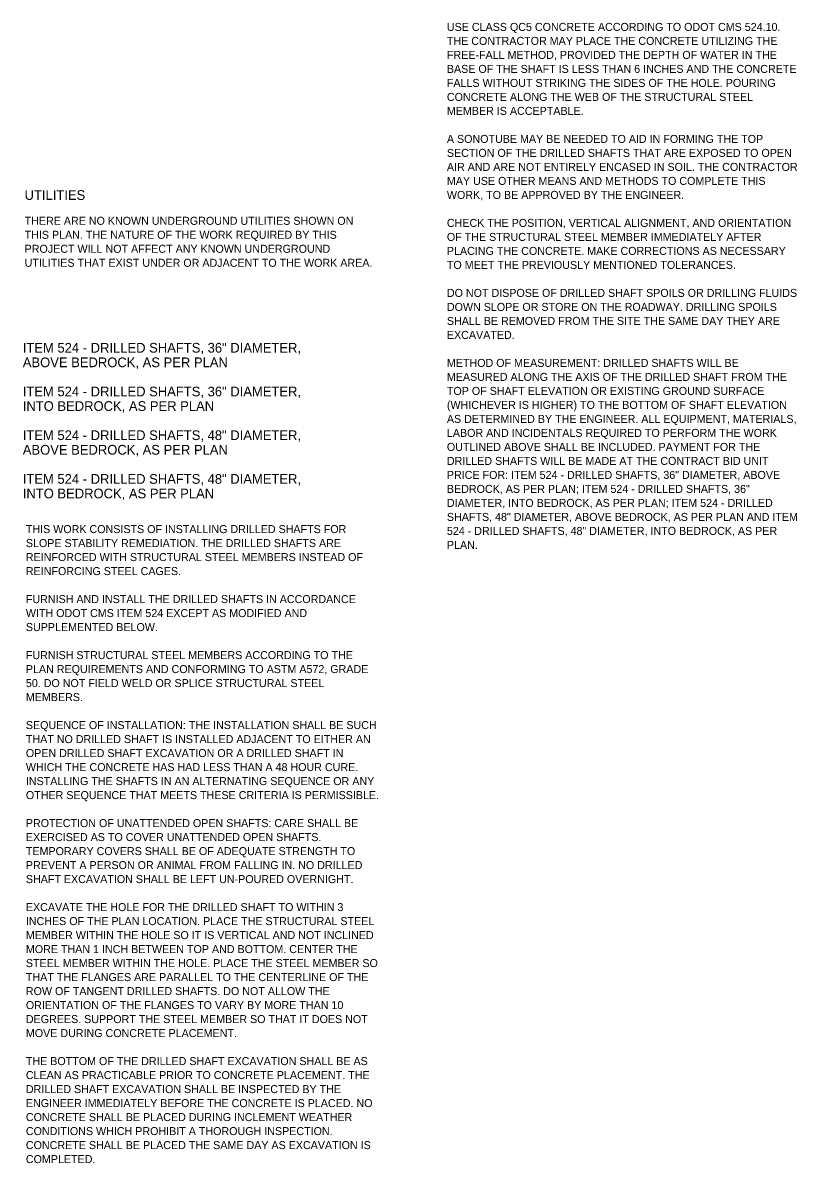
# Model space of a CAD drawing. Extents: x -2.8 to 53.9, y -6 to 15.2.
# Drawn here: x 40.33 to 53.88, y -4.79 to 15.17 of the extents above; entities that cross this region are included whole.
import ezdxf

# ---------------------------------------------------------------- set-up
doc = ezdxf.new("R2010")
doc.units = 0
doc.layers.add('SH_Text', color=7, linetype='Continuous')

msp = doc.modelspace()

# ---------------------------------------------------------------- texts
at = {"layer": 'SH_Text'}
for s, height, p in [('USE CLASS QC5 CONCRETE ACCORDING TO ODOT CMS 524.10. ', 0.14, (47.748, 15.025)), ('THE CONTRACTOR MAY PLACE THE CONCRETE UTILIZING THE ', 0.14, (47.748, 14.78)), ('FREE-FALL METHOD, PROVIDED THE DEPTH OF WATER IN THE ', 0.14, (47.748, 14.535)), ('BASE OF THE SHAFT IS LESS THAN 6 INCHES AND THE CONCRETE ', 0.14, (47.748, 14.29)), ('FALLS WITHOUT STRIKING THE SIDES OF THE HOLE. POURING ', 0.14, (47.748, 14.045)), ('CONCRETE ALONG THE WEB OF THE STRUCTURAL STEEL ', 0.14, (47.748, 13.8)), ('MEMBER IS ACCEPTABLE.', 0.14, (47.748, 13.555)), ('A SONOTUBE MAY BE NEEDED TO AID IN FORMING THE TOP ', 0.14, (47.748, 13.065)), ('SECTION OF THE DRILLED SHAFTS THAT ARE EXPOSED TO OPEN ', 0.14, (47.748, 12.82)), ('AIR AND ARE NOT ENTIRELY ENCASED IN SOIL. THE CONTRACTOR ', 0.14, (47.748, 12.575)), ('MAY USE OTHER MEANS AND METHODS TO COMPLETE THIS ', 0.14, (47.748, 12.33)), ('UTILITIES', 0.17, (40.36, 12.068)), ('WORK, TO BE APPROVED BY THE ENGINEER.', 0.14, (47.748, 12.085)), ('THERE ARE NO KNOWN UNDERGROUND UTILITIES SHOWN ON ', 0.14, (40.36, 11.632)), ('CHECK THE POSITION, VERTICAL ALIGNMENT, AND ORIENTATION ', 0.14, (47.748, 11.595)), ('THIS PLAN. THE NATURE OF THE WORK REQUIRED BY THIS ', 0.14, (40.36, 11.387)), ('OF THE STRUCTURAL STEEL MEMBER IMMEDIATELY AFTER ', 0.14, (47.748, 11.35)), ('PROJECT WILL NOT AFFECT ANY KNOWN UNDERGROUND ', 0.14, (40.36, 11.142)), ('PLACING THE CONCRETE. MAKE CORRECTIONS AS NECESSARY ', 0.14, (47.748, 11.105)), ('UTILITIES THAT EXIST UNDER OR ADJACENT TO THE WORK AREA.', 0.14, (40.36, 10.897)), ('TO MEET THE PREVIOUSLY MENTIONED TOLERANCES.', 0.14, (47.748, 10.86)), ('DO NOT DISPOSE OF DRILLED SHAFT SPOILS OR DRILLING FLUIDS ', 0.14, (47.748, 10.37)), ('DOWN SLOPE OR STORE ON THE ROADWAY. DRILLING SPOILS ', 0.14, (47.748, 10.125)), ('SHALL BE REMOVED FROM THE SITE THE SAME DAY THEY ARE ', 0.14, (47.748, 9.88)), ('EXCAVATED.', 0.14, (47.748, 9.635)), ('ITEM 524 - DRILLED SHAFTS, 36" DIAMETER, ', 0.17, (40.328, 9.395)), ('ABOVE BEDROCK, AS PER PLAN', 0.17, (40.328, 9.14)), ('METHOD OF MEASUREMENT: DRILLED SHAFTS WILL BE ', 0.14, (47.748, 9.145)), ('MEASURED ALONG THE AXIS OF THE DRILLED SHAFT FROM THE ', 0.14, (47.748, 8.9)), ('ITEM 524 - DRILLED SHAFTS, 36" DIAMETER, ', 0.17, (40.328, 8.63)), ('TOP OF SHAFT ELEVATION OR EXISTING GROUND SURFACE ', 0.14, (47.748, 8.655)), ('INTO BEDROCK, AS PER PLAN', 0.17, (40.328, 8.375)), ('(WHICHEVER IS HIGHER) TO THE BOTTOM OF SHAFT ELEVATION ', 0.14, (47.748, 8.41)), ('AS DETERMINED BY THE ENGINEER. ALL EQUIPMENT, MATERIALS, ', 0.14, (47.748, 8.165)), ('ITEM 524 - DRILLED SHAFTS, 48" DIAMETER, ', 0.17, (40.328, 7.865)), ('LABOR AND INCIDENTALS REQUIRED TO PERFORM THE WORK ', 0.14, (47.748, 7.92)), ('OUTLINED ABOVE SHALL BE INCLUDED. PAYMENT FOR THE ', 0.14, (47.748, 7.675)), ('ABOVE BEDROCK, AS PER PLAN', 0.17, (40.328, 7.61)), ('DRILLED SHAFTS WILL BE MADE AT THE CONTRACT BID UNIT ', 0.14, (47.748, 7.43)), ('ITEM 524 - DRILLED SHAFTS, 48" DIAMETER, ', 0.17, (40.328, 7.1)), ('PRICE FOR: ITEM 524 - DRILLED SHAFTS, 36" DIAMETER, ABOVE ', 0.14, (47.748, 7.185)), ('INTO BEDROCK, AS PER PLAN', 0.17, (40.328, 6.845)), ('BEDROCK, AS PER PLAN; ITEM 524 - DRILLED SHAFTS, 36" ', 0.14, (47.748, 6.94)), ('DIAMETER, INTO BEDROCK, AS PER PLAN; ITEM 524 - DRILLED ', 0.14, (47.748, 6.695)), ('SHAFTS, 48" DIAMETER, ABOVE BEDROCK, AS PER PLAN AND ITEM ', 0.14, (47.748, 6.45)), ('THIS WORK CONSISTS OF INSTALLING DRILLED SHAFTS FOR ', 0.14, (40.382, 6.237)), ('524 - DRILLED SHAFTS, 48" DIAMETER, INTO BEDROCK, AS PER ', 0.14, (47.748, 6.205)), ('SLOPE STABILITY REMEDIATION. THE DRILLED SHAFTS ARE ', 0.14, (40.382, 5.992)), ('PLAN. ', 0.14, (47.748, 5.96)), ('REINFORCED WITH STRUCTURAL STEEL MEMBERS INSTEAD OF ', 0.14, (40.382, 5.747)), ('REINFORCING STEEL CAGES.', 0.14, (40.382, 5.502)), ('FURNISH AND INSTALL THE DRILLED SHAFTS IN ACCORDANCE ', 0.14, (40.382, 5.012)), ('WITH ODOT CMS ITEM 524 EXCEPT AS MODIFIED AND ', 0.14, (40.382, 4.767)), ('SUPPLEMENTED BELOW.', 0.14, (40.382, 4.522)), ('FURNISH STRUCTURAL STEEL MEMBERS ACCORDING TO THE ', 0.14, (40.382, 4.032)), ('PLAN REQUIREMENTS AND CONFORMING TO ASTM A572, GRADE ', 0.14, (40.382, 3.787)), ('50. DO NOT FIELD WELD OR SPLICE STRUCTURAL STEEL ', 0.14, (40.382, 3.542)), ('MEMBERS.', 0.14, (40.382, 3.297)), ('SEQUENCE OF INSTALLATION: THE INSTALLATION SHALL BE SUCH ', 0.14, (40.382, 2.807)), ('THAT NO DRILLED SHAFT IS INSTALLED ADJACENT TO EITHER AN ', 0.14, (40.382, 2.562)), ('OPEN DRILLED SHAFT EXCAVATION OR A DRILLED SHAFT IN ', 0.14, (40.382, 2.317)), ('WHICH THE CONCRETE HAS HAD LESS THAN A 48 HOUR CURE. ', 0.14, (40.382, 2.072)), ('INSTALLING THE SHAFTS IN AN ALTERNATING SEQUENCE OR ANY ', 0.14, (40.382, 1.827)), ('OTHER SEQUENCE THAT MEETS THESE CRITERIA IS PERMISSIBLE.', 0.14, (40.382, 1.582)), ('PROTECTION OF UNATTENDED OPEN SHAFTS: CARE SHALL BE ', 0.14, (40.382, 1.092)), ('EXERCISED AS TO COVER UNATTENDED OPEN SHAFTS. ', 0.14, (40.382, 0.847)), ('TEMPORARY COVERS SHALL BE OF ADEQUATE STRENGTH TO ', 0.14, (40.382, 0.602)), ('PREVENT A PERSON OR ANIMAL FROM FALLING IN. NO DRILLED ', 0.14, (40.382, 0.357)), ('SHAFT EXCAVATION SHALL BE LEFT UN-POURED OVERNIGHT.', 0.14, (40.382, 0.112)), ('EXCAVATE THE HOLE FOR THE DRILLED SHAFT TO WITHIN 3 ', 0.14, (40.382, -0.378)), ('INCHES OF THE PLAN LOCATION. PLACE THE STRUCTURAL STEEL ', 0.14, (40.382, -0.623)), ('MEMBER WITHIN THE HOLE SO IT IS VERTICAL AND NOT INCLINED ', 0.14, (40.382, -0.868)), ('MORE THAN 1 INCH BETWEEN TOP AND BOTTOM. CENTER THE ', 0.14, (40.382, -1.113)), ('STEEL MEMBER WITHIN THE HOLE. PLACE THE STEEL MEMBER SO ', 0.14, (40.382, -1.358)), ('THAT THE FLANGES ARE PARALLEL TO THE CENTERLINE OF THE ', 0.14, (40.382, -1.603)), ('ROW OF TANGENT DRILLED SHAFTS. DO NOT ALLOW THE ', 0.14, (40.382, -1.848)), ('ORIENTATION OF THE FLANGES TO VARY BY MORE THAN 10 ', 0.14, (40.382, -2.093)), ('DEGREES. SUPPORT THE STEEL MEMBER SO THAT IT DOES NOT ', 0.14, (40.382, -2.338)), ('MOVE DURING CONCRETE PLACEMENT.', 0.14, (40.382, -2.583)), ('THE BOTTOM OF THE DRILLED SHAFT EXCAVATION SHALL BE AS ', 0.14, (40.382, -3.073)), ('CLEAN AS PRACTICABLE PRIOR TO CONCRETE PLACEMENT. THE ', 0.14, (40.382, -3.318)), ('DRILLED SHAFT EXCAVATION SHALL BE INSPECTED BY THE ', 0.14, (40.382, -3.563)), ('ENGINEER IMMEDIATELY BEFORE THE CONCRETE IS PLACED. NO ', 0.14, (40.382, -3.808)), ('CONCRETE SHALL BE PLACED DURING INCLEMENT WEATHER ', 0.14, (40.382, -4.053)), ('CONDITIONS WHICH PROHIBIT A THOROUGH INSPECTION. ', 0.14, (40.382, -4.298)), ('CONCRETE SHALL BE PLACED THE SAME DAY AS EXCAVATION IS ', 0.14, (40.382, -4.543)), ('COMPLETED.', 0.14, (40.382, -4.788))]:
    msp.add_text(s, height=height, dxfattribs=at).set_placement(p)

doc.saveas('drawing.dxf')
